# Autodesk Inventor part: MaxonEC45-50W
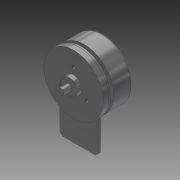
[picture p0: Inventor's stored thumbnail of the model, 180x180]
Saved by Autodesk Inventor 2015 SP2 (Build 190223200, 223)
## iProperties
Created: 2015-08
Part Number: MaxonEC45-50W
Material: Edelstahl
Document SubType Name: Modeling
Designer: ryll
Mass: 265.019 g
Surface Area: 72.2075 cm^2
Volume: 33.1274 cm^3
Density: 8 g/cm^3
Appearance: Halbpoliert
Author: ryll
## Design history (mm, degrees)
sketch "Skizze1"
  geometry: L1 (0, 25.92)-(0, -4.32) reference; L2 (0, 6)-(0, 21.6); L3 (0, 21.6)-(4, 21.6); L4 (4, 21.6)-(4, 21.2); L5 (4, 21.2)-(5.6, 21.2); L6 (5.6, 21.2)-(5.6, 18.25); L7 (5.6, 18.25)-(7.7, 18.25); L8 (7.7, 18.25)-(7.7, 21.4); L9 (7.7, 21.4)-(21.3, 21.4); L10 (21.3, 21.4)-(21.3, 2); L11 (-9, 0)-(32.9, 0); L12 (0, 6)-(-3.2, 6); L13 (-3.2, 6)-(-3.2, 2); L14 (-3.2, 2)-(-9, 2); L15 (-9, 2)-(-9, 0); L16 (-9, 0)-(32.9, 0); L17 (21.3, 2)-(32.9, 2); L18 (32.9, 2)-(32.9, 0); L19 (-17.38, 0)-(41.28, 0) reference; 1 further point
  constraints: 34 end point, 10 perpendicular, 4 horizontal, 3 collinear, 1 vertical
  dimensions: "d0" = 43.2 diameter of L3 L11; "d1" = 4 distance of L2.end L3.end; "d2" = 1.6 distance of L4.end L5.end; "d3" = 2.1 distance of L6.end L7.end; "d4" = 21.3 distance between parallel lines of L2 L10; "d5" = 42.8 diameter of L9 L11; "d6" = 12 diameter of L12 L11; "d7" = 4 diameter of L14 L11; "d8" = 3.2 distance of L2.start L12.end; "d9" = 9 distance between parallel lines of L2 L15; "d10" = 42.4 diameter of L5 L11; "d11" = 36.5 diameter of L7 L11; "d35" = 11.6 distance of L10.end L17.end
revolve "Umdrehung1" sketch "Skizze1" stored, may be unused: angle "d12" = 90 deg
fillet "Rundung1" dims "d13" = 1
sketch "Skizze3"
  geometry: L1 (0, 30.24)-(0, -30.24) reference; L2 (-30.24, 0)-(30.24, 0) reference; 2 further points
  constraints: 1 point on line
  dimensions: "d17" = 11 distance from line of point (0, 11) L2
hole "Bohrung1" sketch "Skizze3" at (0, 11) diameter "d18" = 2.459; stored, may be unused: countersink angle "d22" = 90 deg, drill point angle "d24" = 118 deg; dims "d19" = 6, "d20" = 4, "d21" = 2, "d23" = 3.9
pattern_circular "Runde Anordnung1" dims angle "d26" = 360 deg
sketch "Skizze4"
  geometry: L1 (30.24, 0)-(-30.24, 0) reference; L2 (-14, 15.92)-(-14, 40.5); L3 (-14, 40.5)-(14, 40.5); L4 (14, 40.5)-(14, 15.92); L5 (0, 52.92)-(0, -34.02) reference; A1 r 21.2 centre (0, 0) between (14, 15.92) and (-14, 15.92) reference; A2 r 21.2 centre (0, 0) between (14, 15.92) and (-14, 15.92); 1 further point
  constraints: 6 end point, 4 point on circle, 2 parallel, 1 centre point, 1 concentric, 1 other
  dimensions: "d28" = 28 distance of L2.end L3.end; "d29" = 40.5 distance between parallel lines of L3 L1
extrude "Extrusion2" join sketch "Skizze4" distance "d30" = 1.6; taper "d31" = 0 deg
chamfer "Fase1" distance "d32" = 2; stored, may be unused: second distance "d33" = 2, angle "d34" = 45 deg
node "Volumenkörper1"
